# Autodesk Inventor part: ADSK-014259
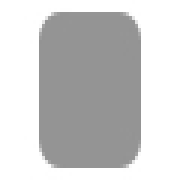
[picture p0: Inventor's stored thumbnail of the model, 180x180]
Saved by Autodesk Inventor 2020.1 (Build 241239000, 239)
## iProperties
Created: 2019-01
Part Number: ADSK-014259
Material: Stahl, weich
Document SubType Name: Modeling
Designer: lutzd
Language: de-DE
Size Designation: 5 x 89,384472 x 39,384472
Categories: <MemberInstance><Categories><Category DisplayName="Sonstige Bauteile" InternalName="5aa15e00-363f-49f2-933f-16f664388e3f" Mnemonic="OTHER"><Category DisplayName
Mass: 137.332 g
Surface Area: 82.4257 cm^2
Volume: 17.4945 cm^3
Density: 7.85 g/cm^3
Appearance: Semi-Polished(8)
IsCustomPart: 1
Title: end cap
Author: lutzd
Revision Number: -
Dimensions: 39,4x89,4x5 mm
Mass: 0,137 kg
DocNumber: ADSK-014259
Folder: 01 - Themengebiete\Simplification\01 - Packaging machine\ADSK-014200\Frame\
VDS_Category: 3D Komponenten
VDS_NumSchm: Autodesk
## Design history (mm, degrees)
sketch "Sketch1"
  geometry: L1 (0, 20.175)-(0, -21.446); L2 (-20.203, 0)-(20.169, 0); L3 (-19.692, 44.692)-(19.692, 44.692); L4 (19.692, 44.692)-(19.692, -44.692); L5 (19.692, -44.692)-(-19.692, -44.692); L6 (-19.692, -44.692)-(-19.692, 44.692); 1 further point
  constraints: 12 end point, 2 horizontal, 2 parallel, 2 point on line, 1 perpendicular, 1 vertical
  dimensions: "d0" = 89.38447 distance between parallel lines of L5 L3 (= height); "d1" = 44.69224 distance between parallel lines of L2 L3 (= 0.5 x height); "d2" = 39.38447 distance between parallel lines of L6 L4 (= width); "d3" = 19.69224 distance between parallel lines of L6 L1 (= 0.5 x width)
extrude "Extrusion1" new body sketch "Sketch1" distance "d4" = 5 (= thickness); taper "d5" = 0 deg
fillet "Fillet1" dims "d6" = 5 (= fillet), "d7" = 0, "fillet" = 5 [user parameter; used in 1 equation term]
chamfer "Chamfer1" distance "d8" = 0 (computed from chamfer); stored, may be unused: second distance "d9" = 2, angle "d10" = 45 deg; dims "d11" = 0, "chamfer" = 0 [user parameter; used in 1 equation term]
body "Solid1"
other parameters: "thickness" = 5 [user parameter; used in 1 equation term], "width" = 39.38447 [user parameter; used in 2 equation terms], "height" = 89.38447 [user parameter; used in 2 equation terms]
